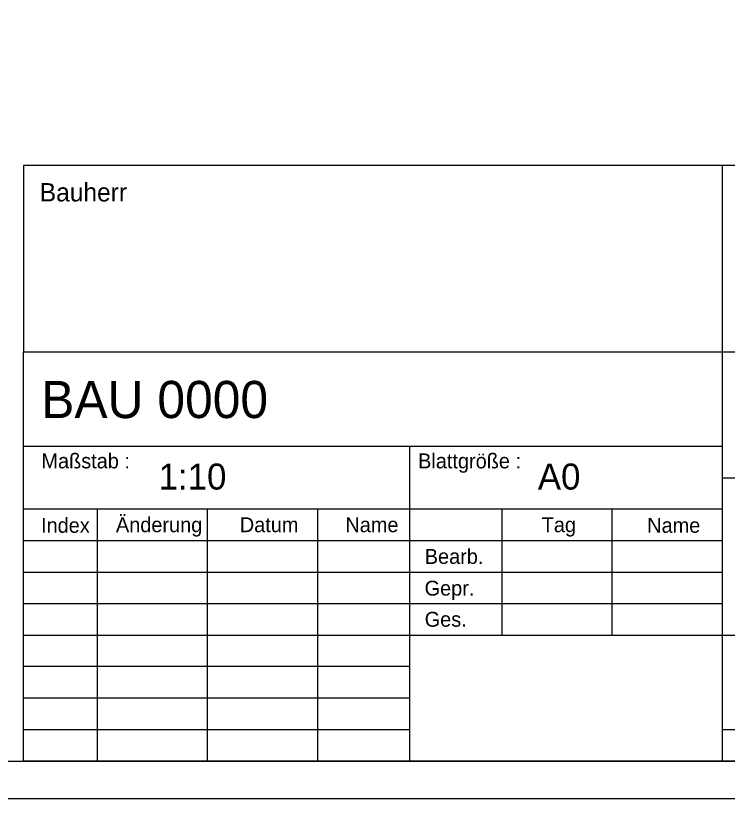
# Model space of a CAD drawing. Extents: x 0 to 11.9, y 0 to 8.4.
# Drawn here: x 10.051 to 11.007, y 0 to 1.051 of the extents above; entities that cross this region are included whole.
import ezdxf

# ---------------------------------------------------------------- set-up
doc = ezdxf.new("R2010")
doc.units = 0
doc.layers.add('90_Plankopf', color=7, linetype='Continuous')

msp = doc.modelspace()

# ---------------------------------------------------------------- linework, layer by layer
at = {"layer": '90_Plankopf'}
for p, q in [((11.84, 0.8499), (10.0612, 0.8499)), ((10.0612, 0.8499), (10.0612, 0.5999)), ((11, 0.5999), (11, 0.8499)), ((10.0612, 0.5999), (11.84, 0.5999)), ((10.0612, 0.05), (10.0612, 0.5999)), ((10.0612, 0.5999), (11.84, 0.5999)), ((11, 0.05), (11, 0.5999)), ((10.0612, 0.473), (11, 0.473)), ((10.58, 0.05), (10.58, 0.473)), ((11, 0.4307), (11.84, 0.4307)), ((10.0612, 0.3887), (11, 0.3887)), ((10.16, 0.3884), (10.16, 0.05)), ((10.3083, 0.05), (10.3083, 0.3884)), ((10.4565, 0.05), (10.4565, 0.3884)), ((10.7035, 0.3884), (10.7035, 0.2192)), ((10.8518, 0.2192), (10.8518, 0.3884)), ((10.0612, 0.3463), (11, 0.3463)), ((10.0612, 0.3038), (11, 0.3038)), ((10.0612, 0.2615), (11, 0.2615)), ((10.0612, 0.2192), (11, 0.2192)), ((10.0612, 0.2192), (11, 0.2192)), ((10.58, 0.2192), (11, 0.2192)), ((11, 0.2192), (11.84, 0.2192)), ((10.58, 0.1769), (10.0612, 0.1769)), ((10.58, 0.1346), (10.0612, 0.1346)), ((10.0612, 0.0923), (10.58, 0.0923)), ((11, 0.0923), (11.84, 0.0923)), ((11.84, 0.05), (10.0612, 0.05)), ((10.0612, 0.05), (10.58, 0.05)), ((10.178, 0.05), (11.84, 0.05)), ((10.178, 0.05), (11.84, 0.05))]:
    msp.add_line(p, q, dxfattribs=at)
for points in [[(0, 0), (11.89, 0), (11.89, 8.41), (0, 8.41)], [(0.25, 0.05), (11.84, 0.05), (11.84, 8.36), (0.25, 8.36)]]:
    msp.add_lwpolyline(points, close=True, dxfattribs=at)

# ---------------------------------------------------------------- texts
for s, height, p in [('Bauherr', 0.02464, (10.083, 0.8017)), ('BAU 0000      ', 0.05, (10.0849, 0.5107)), ('Maßstab :', 0.02, (10.0852, 0.4432)), ('Blattgröße :', 0.019999, (10.5912, 0.4432)), ('1:10     ', 0.035, (10.2426, 0.4147)), ('A0       ', 0.035, (10.752, 0.4147)), ('Änderung', 0.02, (10.1853, 0.3575)), ('Index', 0.02, (10.0847, 0.3567)), ('Datum', 0.02, (10.3517, 0.3575)), ('Name', 0.02, (10.4935, 0.3575)), ('Tag', 0.02, (10.7572, 0.3575)), ('Name', 0.02, (10.8989, 0.3567)), ('Bearb.', 0.02, (10.6001, 0.3149)), ('Gepr.', 0.02, (10.5999, 0.2723)), ('Ges.', 0.02, (10.6, 0.2305))]:
    msp.add_text(s, height=height, dxfattribs=at).set_placement(p)

doc.saveas('drawing.dxf')
